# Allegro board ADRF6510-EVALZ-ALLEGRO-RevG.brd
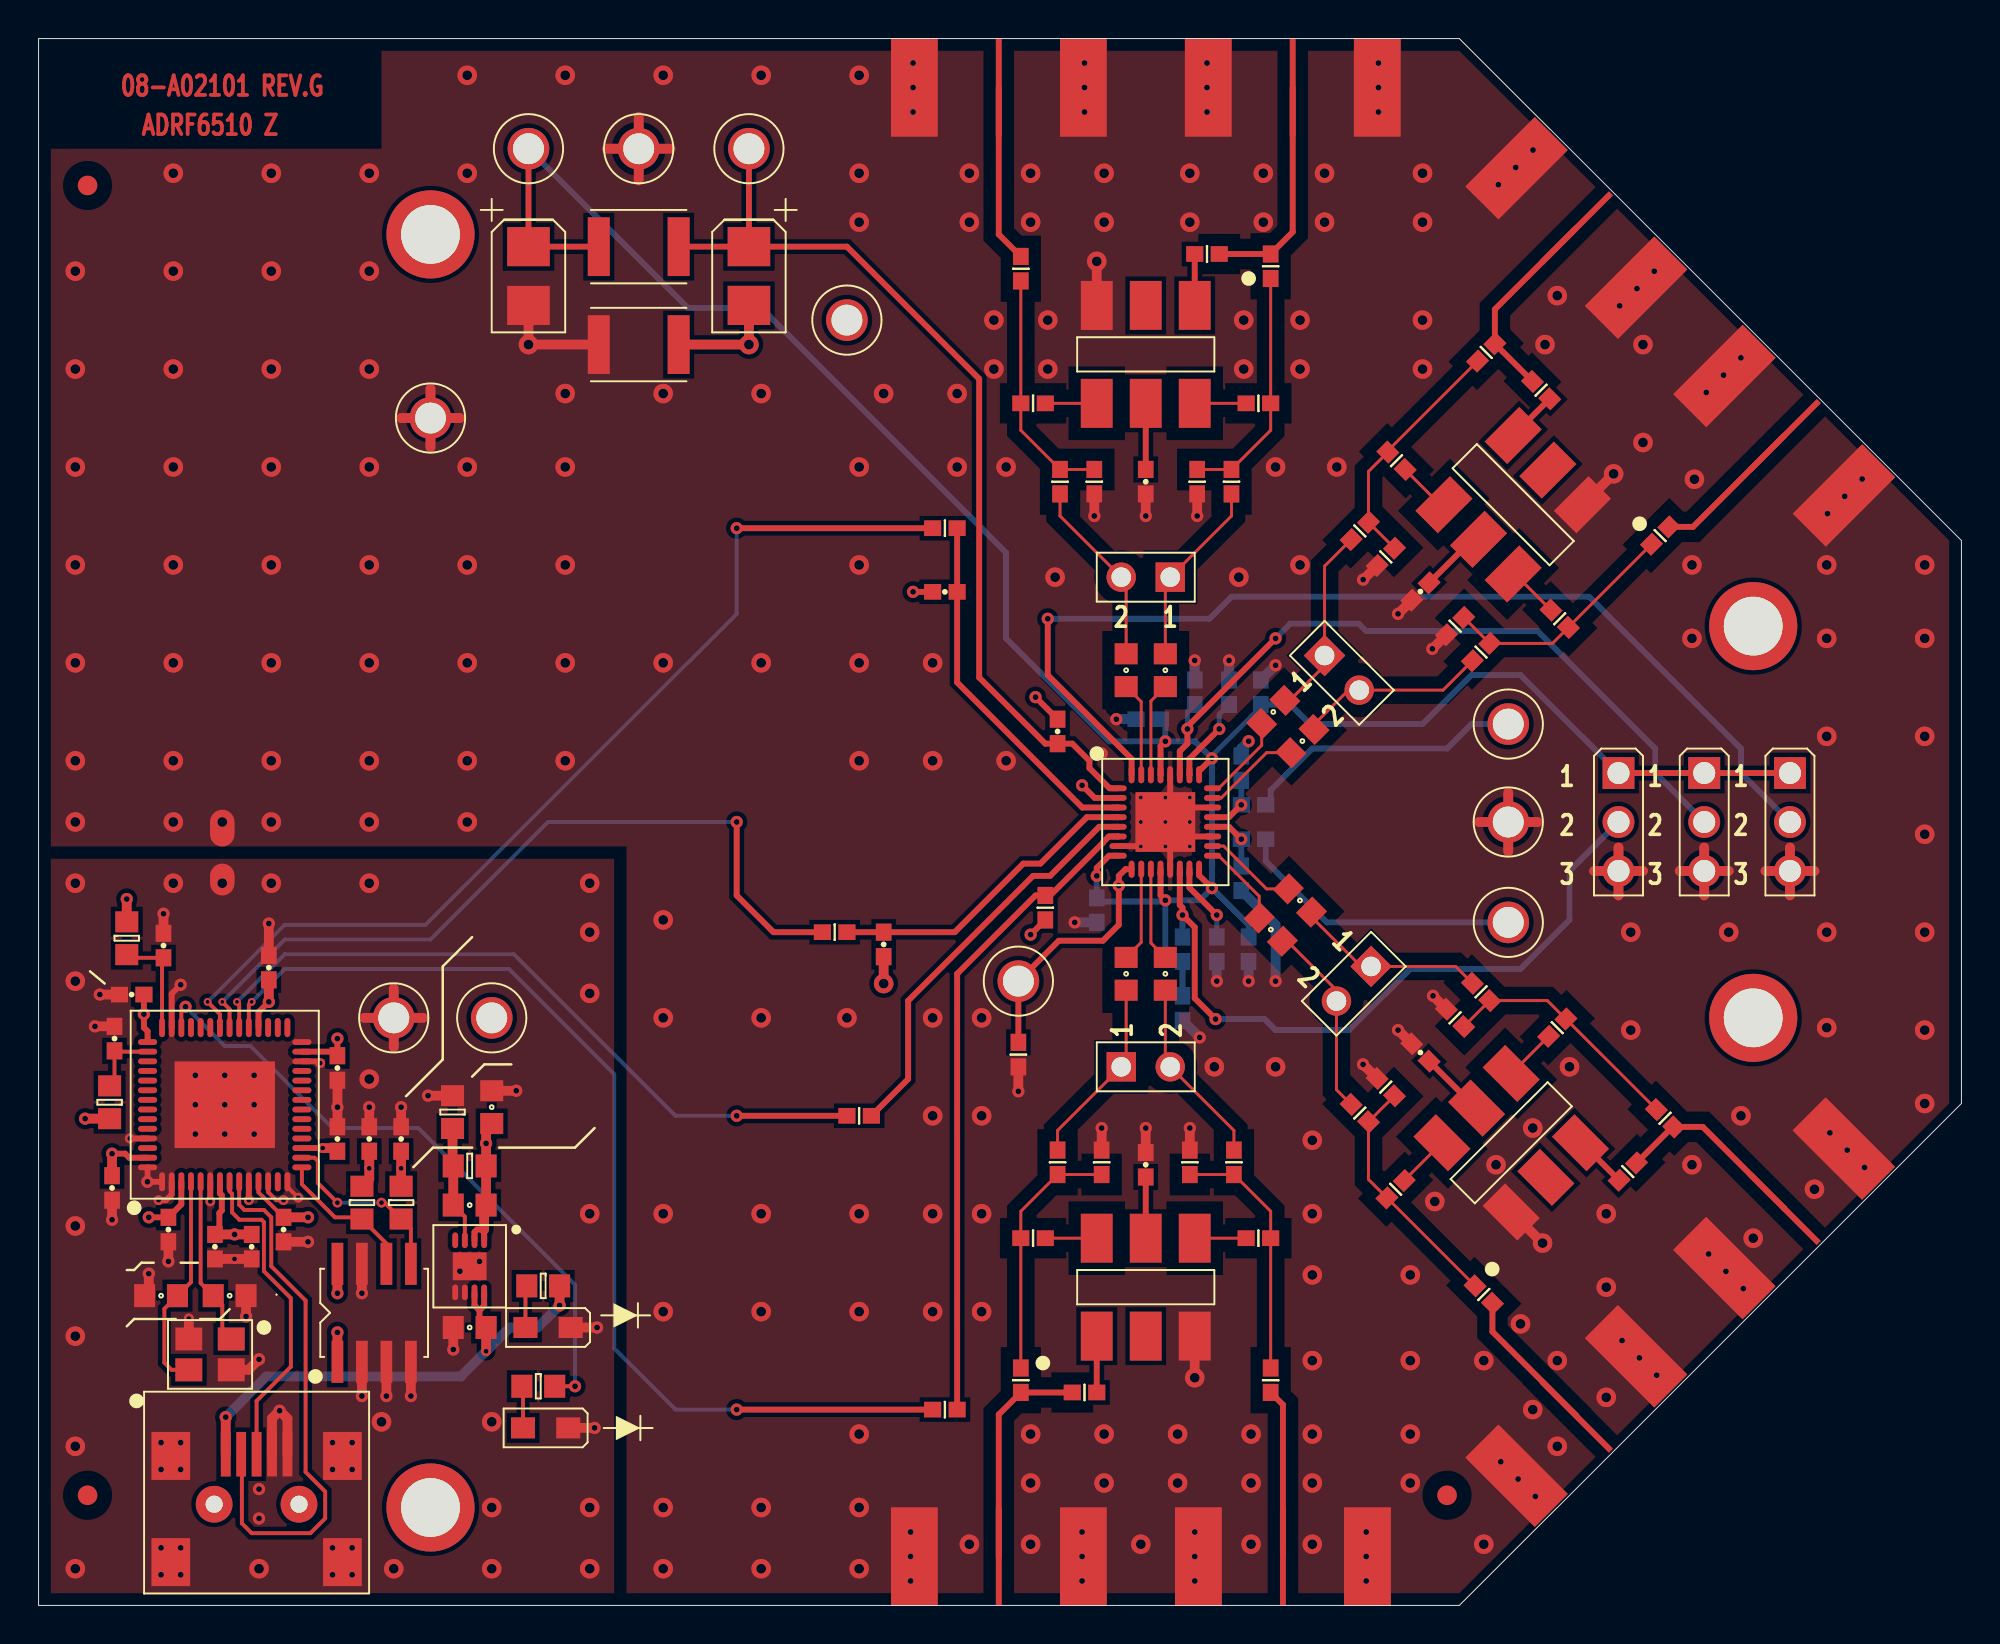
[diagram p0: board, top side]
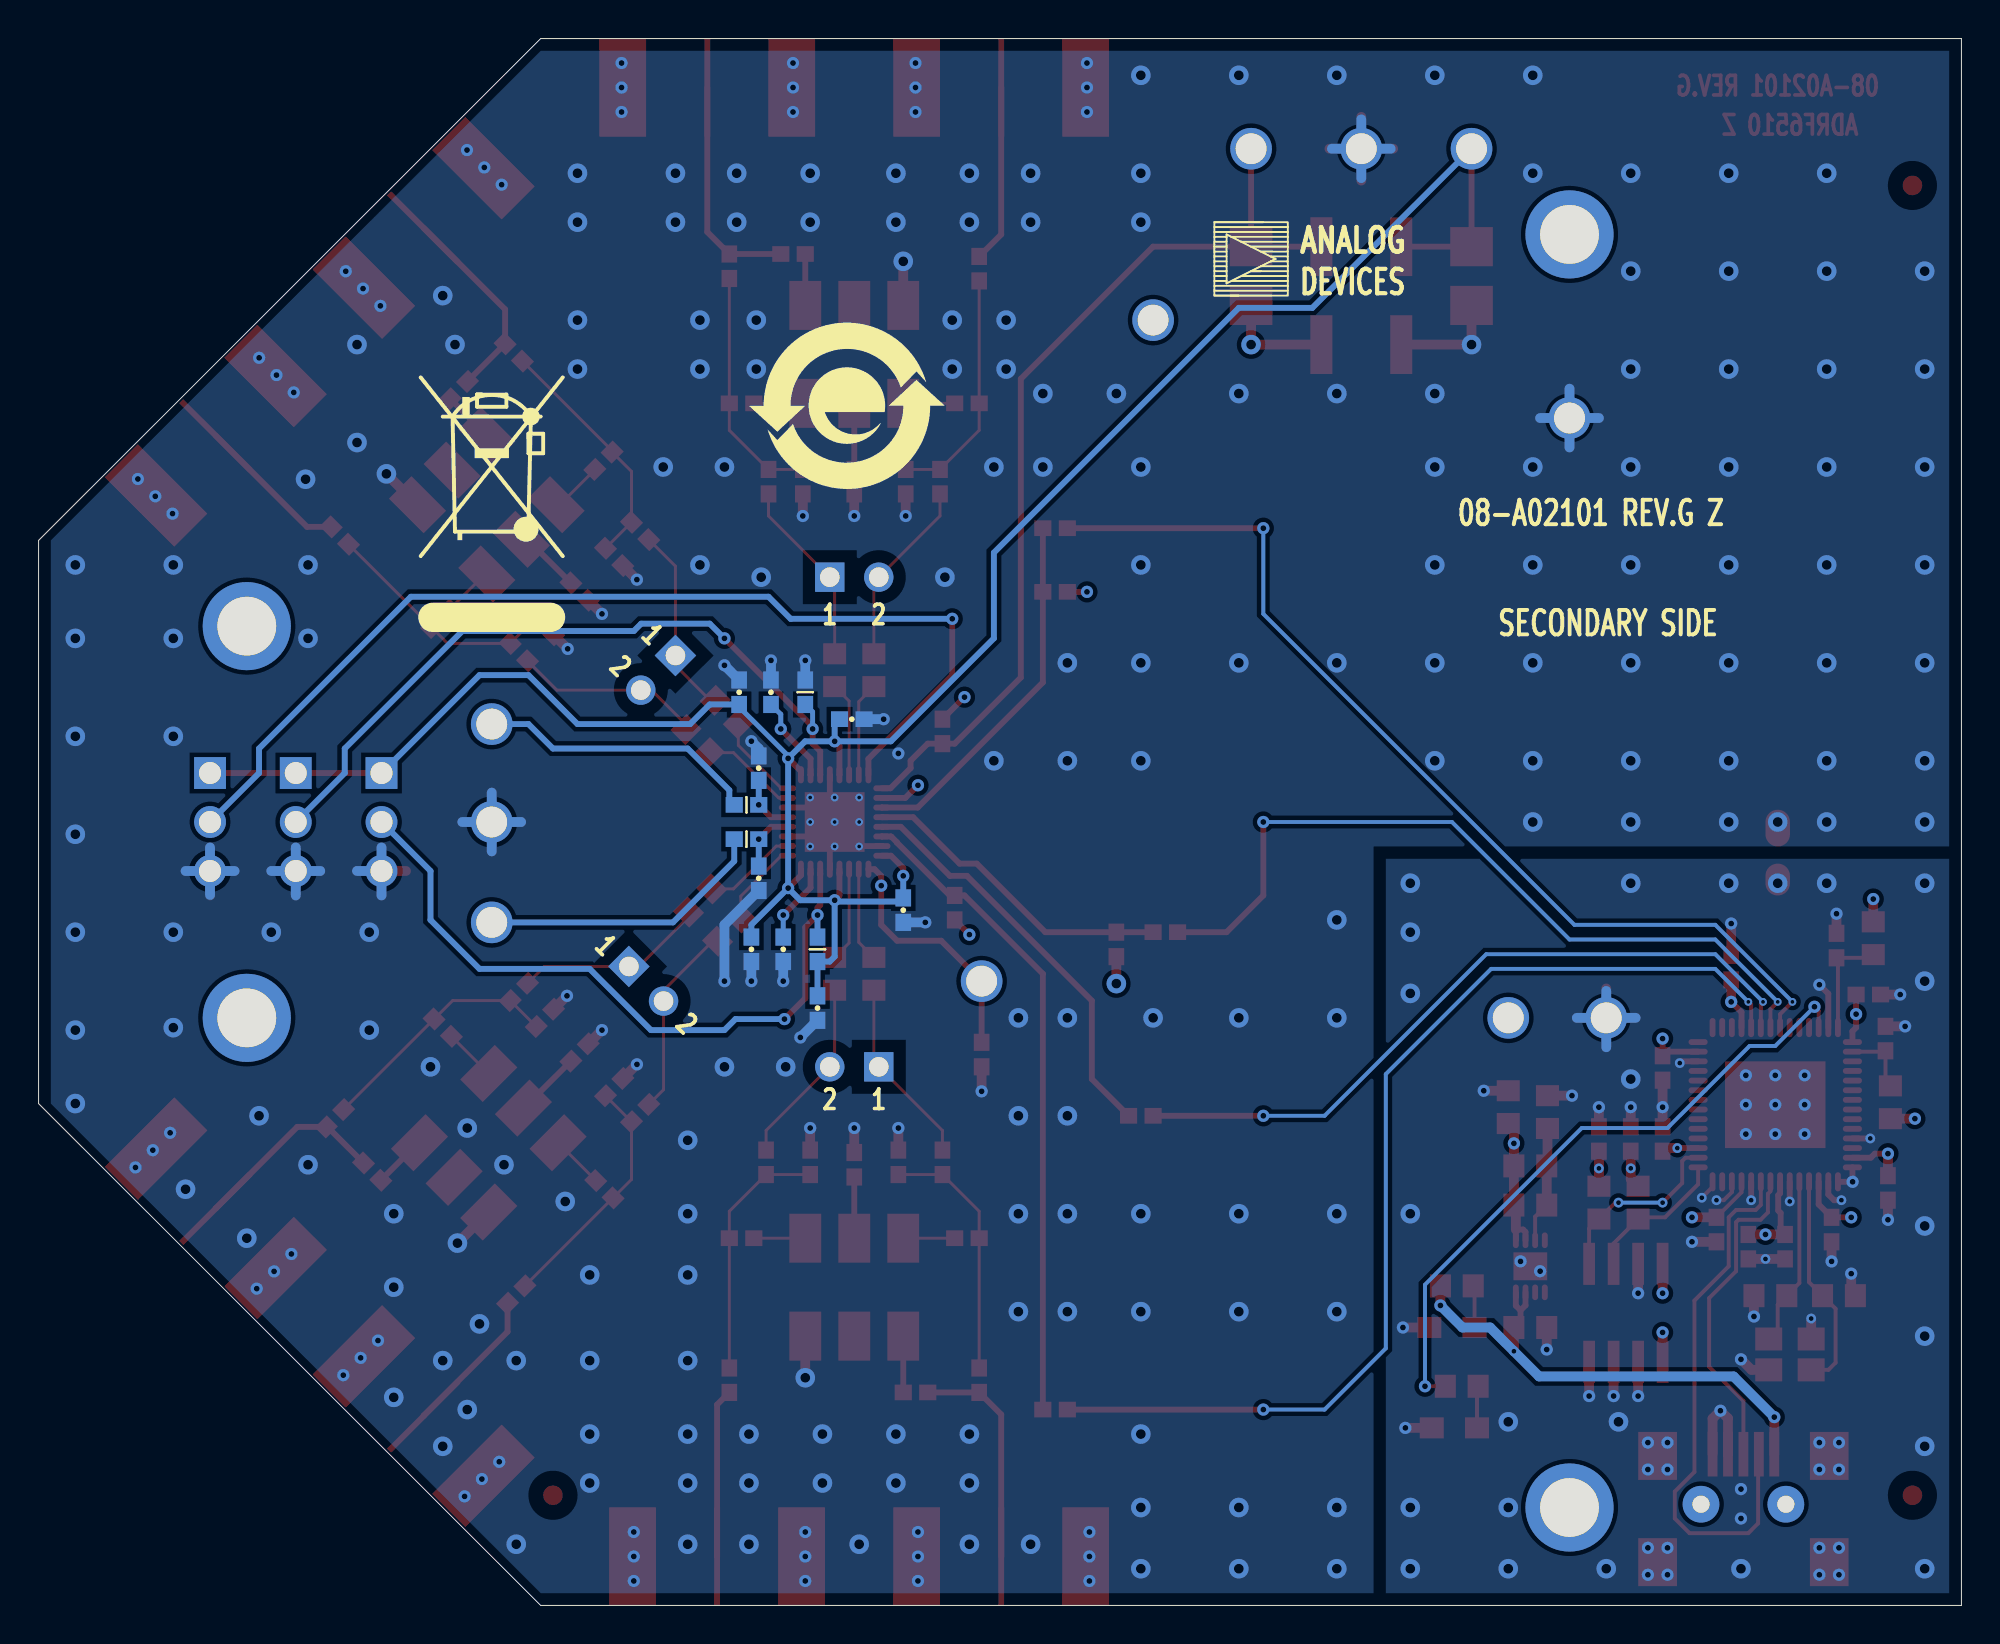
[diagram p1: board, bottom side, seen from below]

Outline 99.69 x 81.28 mm; copper layers: TOP, L2_GND, L3_GND, BOTTOM. Coordinates in mm from the lower left corner of the outline.
Outline path: 0,81.28 0,0 73.66,0 99.69,26.04 99.69,55.25 73.66,81.28 0,81.28

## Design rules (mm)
net group 50_OHMS: nets UNNAMED_2_CNBNC5P_I37_CNTR UNNAMED_2_CNBNC5P_I39_CNTR UNNAMED_2_CNBNC5P_I62_CNTR UNNAMED_2_CNBNC5P_I63_CNTR UNNAMED_2_CNBNC5P_I80_CNTR UNNAMED_2_CNBNC5P_I81_CNTR UNNAMED_2_CNBNC5P_I127_CNTR UNNAMED_2_CNBNC5P_I129_CNTR
net group HIGH_Z: nets UNNAMED_2_ADRF6510_I1_INM1 UNNAMED_2_ADRF6510_I1_INM2 UNNAMED_2_ADRF6510_I1_INP1 UNNAMED_2_ADRF6510_I1_INP2 UNNAMED_2_ADRF6510_I1_OPM1 UNNAMED_2_ADRF6510_I1_OPM2 UNNAMED_2_ADRF6510_I1_OPP1 UNNAMED_2_ADRF6510_I1_OPP2 UNNAMED_2_CAP_I21_N2 UNNAMED_2_CAP_I22_N2 UNNAMED_2_CAP_I59_N2 UNNAMED_2_CAP_I60_N2 UNNAMED_2_CAP_I96_N2 UNNAMED_2_CAP_I97_N2 UNNAMED_2_CAP_I111_N1 UNNAMED_2_CAP_I112_N1 UNNAMED_2_RES_I24_N2 UNNAMED_2_RES_I26_N2 UNNAMED_2_RES_I29_N2 UNNAMED_2_RES_I32_N1 UNNAMED_2_RES_I50_N1 UNNAMED_2_RES_I50_N2 UNNAMED_2_RES_I51_N1 UNNAMED_2_RES_I51_N2 UNNAMED_2_RES_I82_N1 UNNAMED_2_RES_I86_N1 UNNAMED_2_RES_I87_N2 UNNAMED_2_RES_I90_N1 UNNAMED_2_RES_I114_N1 UNNAMED_2_RES_I116_N2 UNNAMED_2_RES_I120_N2 UNNAMED_2_RES_I123_N1

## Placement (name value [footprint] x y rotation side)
C1  10UF  [C3528]  36.83 68.96 270 top
C2  10UF  [C3528]  25.4 68.96 270 top
C3  0.1UF  [C0402]  57.4 22.86 270 top
C4  0.1UF  [C0402]  52.83 45.34 90 top
C5  0.1UF  [C0402]  54.86 36.07 270 bottom
C6  0.1UF  [C0402]  57.4 58.29 90 top
C7  100NF  [C0603H62]  56.39 32.77 270 top
C8  100NF  [C0603H62]  58.42 32.77 270 top
C9  100NF  [C0603H62]  58.42 48.51 270 top
C10  100NF  [C0603H62]  56.39 48.51 270 top
C11  0.1UF  [C0402]  59.31 30.99 270 bottom
C12  0.1UF  [C0402]  57.53 45.97 180 bottom
C13  0.001UF  [C0402]  61.09 34.04 270 bottom
C14  0.001UF  [C0402]  61.72 47.37 90 bottom
C15  0.1UF  [C0402]  62.74 34.04 270 bottom
C16  0.1UF  [C0402]  63.37 47.37 90 bottom
C17  0.1UF  [C0402]  62.36 43.43 270 bottom
C18  0.1UF  [C0402]  62.36 37.72 270 bottom
C19  100NF  [C0603H62]  64.02 46.35 45 top
C20  100NF  [C0603H62]  65.52 44.84 45 top
C21  100NF  [C0603H62]  65.4 36.57 315 top
C22  100NF  [C0603H62]  63.89 35.06 315 top
C23  0.1UF  [C0402]  71.65 52.6 45 top
C24  0.1UF  [C0402]  71.65 28.68 315 top
C27  330pF  [C0402]  46.99 52.58 180 top
C28  330pF  [C0402]  43.81 34.29 270 top
C35  0.1UF  [C0402]  4.83 31.69 180 top
C36  0.1UF  [C0402]  3.81 21.66 270 top
C37  0.1UF  [C0402]  6.48 34.23 90 top
C38  10pF  [C0402]  17.15 24.2 90 top
C39  0.1UF  [C0402]  18.8 24.2 90 top
C40  0.1UF  [C0402]  15.49 24.2 90 top
C41  0.1UF  [C0402]  15.49 27.88 270 top
C42  0.1UF  [C0402]  11.94 33.09 90 top
C44  0.1UF  [C0402]  12.7 19.5 270 top
C45  0.1UF  [C0402]  3.94 29.4 90 top
C46  0.1UF  [C0402]  11.05 18.61 270 top
C47  1UF  [C0603]  22.35 14.42 180 top
C48  10pF  [C0402]  6.73 19.5 270 top
C49  0.1UF  [C0402]  9.14 18.61 270 top
C50  1000pF  [C0603]  22.35 20.77 180 top
C51  22PF  [C0603]  9.91 16.07 0 top
C52  1UF  [C0603]  23.5 25.85 90 top
C54  22PF  [C0603]  6.35 16.07 180 top
COM  GRN  [CNLOOPTP]  76.2 40.64 0 top
COMA  GRN  [CNLOOPTP]  31.12 75.56 0 top
COMB  GRN  [CNLOOPTP]  20.32 61.59 0 top
COMD  VIOLET  [CNLOOPTP]  41.91 66.67 0 top
CR1  SML-210MTT86  [LED0805]  26.42 14.42 180 top
CR2  SML-210MTT86  [LED0805]  26.29 9.21 180 top
DGND  BLK  [CNLOOPTP]  18.41 30.48 270 top
INM1_SE_P  JOHNSON142-0701-851  [CNJOHNSON142-0701-851]  65.02 78.74 90 top
INM2_SE_P  JOHNSON142-0701-851  [CNJOHNSON142-0701-851]  64.52 2.54 270 top
INP1  JOHNSON142-0701-851  [CNJOHNSON142-0701-851]  49.78 78.74 90 top
INP2  JOHNSON142-0701-851  [CNJOHNSON142-0701-851]  49.78 2.54 270 top
L1  33uH  [L1812-3]  31.12 65.41 180 top
L2  33uH  [L1812-3]  31.12 70.48 180 top
NOREF  -  []  697.99 -250.7 0 top
NOREF#2  -  [unnamed#2]  20.32 5.08 0 top
NOREF#3  -  []  73.66 0 90 top
NOREF#4  -  []  0 0 0 top
NOREF#5  -  [unnamed#2]  73.03 5.72 0 top
NOREF#6  -  [unnamed#2]  88.9 30.48 0 top
NOREF#7  -  []  0 0 0 top
NOREF#8  -  []  0 0 0 top
NOREF#9  -  []  -93.98 -259.08 0 top
NOREF#10  -  [unnamed#2]  2.54 73.66 0 top
NOREF#11  -  []  39.37 -116.71 0 top
NOREF#12  -  []  0 0 90 top
NOREF#13  -  []  73.66 0 90 top
NOREF#14  -  []  37.47 92.71 0 top
NOREF#15  -  [unnamed#2]  88.9 50.8 0 top
NOREF#16  -  [unnamed#2]  2.54 5.72 0 top
NOREF#17  -  []  0 0 90 top
NOREF#18  -  [unnamed#2]  20.32 71.12 0 top
NOREF#19  -  []  517.14 -106.05 0 top
NOREF#20  -  []  0 0 0 top
NOREF#21  -  []  283.97 -102.36 0 top
NOREF#22  -  []  0 81.28 270 top
NOREF#23  -  []  504.82 143.13 0 top
NOREF#24  -  []  498.48 -125.1 0 top
NOREF#25  -  []  57.79 62.23 180 bottom
NOREF#26  -  []  66.93 67.39 180 bottom
NOREF#27  -  []  38.73 67.94 180 bottom
OPM1_SE_P  JOHNSON142-0701-851  [CNJOHNSON142-0701-851]  90.51 60.68 45 top
OPM2_SE_P  JOHNSON142-0701-851  [CNJOHNSON142-0701-851]  90.5 20.6 315 top
OPP1  JOHNSON142-0701-851  [CNJOHNSON142-0701-851]  79.73 71.46 45 top
OPP2  JOHNSON142-0701-851  [CNJOHNSON142-0701-851]  79.73 9.82 315 top
P1  BERG69157-102  [CNBERG69157-102]  56.13 27.94 0 top
P2  MOLEX22-03-2031  [CNMOLEX22-03-2031]  90.81 43.18 270 top
P3  MOLEX22-03-2031  [CNMOLEX22-03-2031]  86.36 43.18 270 top
P4  MOLEX22-03-2031  [CNMOLEX22-03-2031]  81.92 43.18 270 top
P5  897-43-005-00-100001  [CNTYCO-1734035-2]  11.3 6.93 0 top
P6  BERG69157-102  [CNBERG69157-102]  58.67 53.34 180 top
P7  BERG69157-102  [CNBERG69157-102]  66.67 49.28 315 top
P8  BERG69157-102  [CNBERG69157-102]  69.09 33.15 225 top
R1  10K  [R0402]  52.2 36.2 270 top
R2  0  [R0402]  50.8 28.58 90 top
R3  10K  [R0402]  59.31 34.04 270 bottom
R4  10K  [R0402]  59.94 47.37 90 bottom
R5  0  [R0402]  62.99 41.53 0 bottom
R6  0  [R0402]  62.99 39.75 0 bottom
R7  300  [R0402]  68.5 55.74 45 top
R8  300  [R0402]  74.79 49.45 45 top
R9  300  [R0402]  74.79 31.83 315 top
R10  300  [R0402]  68.5 25.54 315 top
R11  TBD0402  [R0402]  73.44 50.8 225 top
R12  TBD0402  [R0402]  69.85 54.39 225 top
R13  TBD0402  [R0402]  69.85 26.89 135 top
R14  TBD0402  [R0402]  73.44 30.48 135 top
R19  0  [R0402]  70.4 59.38 315 top
R20  0  [R0402]  78.87 51.18 315 top
R29  100  [R0402]  46.99 55.88 0 top
R30  100  [R0402]  41.28 34.92 0 top
R31  0  [R0402]  60.58 70.1 180 top
R32  0  [R0402]  54.23 11.05 0 top
R33  0  [R0402]  42.55 25.4 0 top
R34  0  [R0402]  46.99 10.16 0 top
R35  0  [R0402]  78.74 29.97 225 top
R36  0  [R0402]  70.36 21.59 225 top
R37  TBD0402  [R0402]  75.06 65 45 top
R38  TBD0402  [R0402]  84.33 25.27 315 top
R39  TBD0402  [R0402]  84.07 55.5 45 top
R40  TBD0402  [R0402]  74.93 16.13 315 top
R41  0  [R0402]  77.9 63.04 315 top
R42  0  [R0402]  82.4 22.5 225 top
R43  TBD0402  [R0402]  50.93 69.34 90 top
R44  TBD0402  [R0402]  63.88 11.68 270 top
R45  TBD0402  [R0402]  63.88 69.47 90 top
R46  TBD0402  [R0402]  50.93 11.68 270 top
R47  0  [R0402]  63.25 62.36 180 top
R48  0  [R0402]  51.56 62.36 180 top
R49  0  [R0402]  51.56 19.05 0 top
R50  0  [R0402]  63.25 19.05 0 top
R51  TBD0402  [R0402]  55.12 22.99 90 top
R52  TBD0402  [R0402]  59.69 22.99 90 top
R53  0  [R0402]  52.83 22.99 270 top
R54  0  [R0402]  61.98 22.99 270 top
R55  TBD0402  [R0402]  60.07 58.29 270 top
R56  TBD0402  [R0402]  54.74 58.29 270 top
R57  0  [R0402]  61.85 58.29 90 top
R58  0  [R0402]  52.96 58.29 90 top
R59  2K  [R0603]  18.8 20.9 270 top
R60  2K  [R0603]  16.76 20.9 270 top
R61  2K  [R0603]  25.91 11.37 180 top
R62  100K  [R0603]  3.68 26.1 90 top
R64  100K  [R0603]  4.57 34.61 270 top
R65  2K  [R0603]  26.16 16.58 180 top
R69  78.7K  [R0603]  21.46 25.59 90 top
R70  140K  [R0603]  22.35 22.8 180 top
SNS1  SNS  [NCSNS50MIL]  9.52 40.01 270 top
T1  ADT8-1T+  [MINICKCD637]  57.4 64.9 180 top
T2  ADT8-1T+  [MINICKCD637]  57.4 16.51 0 top
T3  ADT8-1T+  [MINICKCD637]  76.45 57.1 135 top
T4  ADT8-1T+  [MINICKCD637]  76.35 24 45 top
TRIM  BLK  [CNLOOPTP]  50.8 32.38 0 top
U1  ADRF6510ACPZ  [QFN32_5X5_PAD3_1X3_1]  58.42 40.64 270 top
U2  24LC64-I-SN  [SO8]  17.4 15.18 0 top
U3  ADP3334ACPZ  [QFN8_3X3_PAD1_75X1_45]  22.35 17.59 180 top
U4  CY7C68013A-56LTXC  [QFN56_8X8_PAD5_2X4_5]  9.65 25.98 0 top
UNK3V3_USB  BLK  [CNLOOPTP]  23.5 30.48 270 top
VGAIN  WHT  [CNLOOPTP]  76.2 45.72 0 top
VOCM  ORG  [CNLOOPTP]  76.2 35.43 0 top
VPS  RED  [CNLOOPTP]  25.4 75.56 0 top
VPSD  YEL  [CNLOOPTP]  36.83 75.56 0 top
Y1  24.000000MEGHZ  [XTALNX3225]  8.89 13.02 180 top

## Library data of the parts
C1 C2 = CAPP: User Part Number: UPN; Tolerance: 10; part number: CAPP_SM-10UF,16V,10,E000695,C3528; tolerance: 10
C3-C6 C11 C12 C15-C18 C23 C24 C35-C37 C39-C42 C44-C46 C49 = CAP: Tolerance: 10; User Part Number: UPN; alternate symbols: (C0402H22_ALT,C0201-2); part number: CAP_SM-0.1UF,16V,10,E007200,C0402; tolerance: 10
C7-C10 C19-C22 = CAP: Tolerance: 20; User Part Number: UPN; alternate symbols: (C0402H22_ALT,C0201-2); part number: CAP_SM-100NF,25V,20,E000372,C0603H62; tolerance: 20
C13 C14 = CAP: Tolerance: 10; User Part Number: UPN; alternate symbols: (C0402H22_ALT,C0201-2); part number: CAP_SM-0.001UF,50V,10,E006276,C0402; tolerance: 10
C27 C28 = CAP: Tolerance: 10; User Part Number: UPN; alternate symbols: (C0402H22_ALT,C0201-2); part number: CAP_SM-330PF,50V,10,E012647,C0402; tolerance: 10
C38 C48 = CAP: Tolerance: 5; User Part Number: UPN; alternate symbols: (C0402H22_ALT,C0201-2); part number: CAP_SM-10PF,50V,5,E007982,C0402; tolerance: 5
C47 C52 = CAP: Tolerance: 10; User Part Number: UPN; alternate symbols: (C0402H22_ALT,C0201-2); part number: CAP_SM-1UF,25V,10,E006992,C0603; tolerance: 10
C50 = CAP: Tolerance: 5; User Part Number: UPN; alternate symbols: (C0402H22_ALT,C0201-2); part number: CAP_SM-1000PF,50V,5,E007908,C0603; tolerance: 5
C51 C54 = CAP: Tolerance: 5; User Part Number: UPN; alternate symbols: (C0402H22_ALT,C0201-2); part number: CAP_SM-22PF,50V,5,E000411,C0603; tolerance: 5
COM COMA COMB = CNTP1P: User Part Number: UPN; part number: CNTP1P_TH-GRN,E000952,CNLOOPTP
COMD = CNTP1P: User Part Number: UPN; part number: CNTP1P_TH-VIOLET,E000954,CNLOOPTP
CR1 CR2 = DIOLED: Tolerance: N/A; User Part Number: UPN; part number: DIOLED_SM-SML-210MTT86,2.2V,N/A,E011181,LED0805; tolerance: N/A
DGND TRIM UNK3V3_USB = CNTP1P: User Part Number: UPN; part number: CNTP1P_TH-BLK,E000948,CNLOOPTP
INM1_SE_P INM2_SE_P INP1 INP2 OPM1_SE_P OPM2_SE_P OPP1 OPP2 = CNBNC5P: User Part Number: UPN; part number: CNBNC5P_SM-JOHNSON142-0701-851,E000923,CNJOHNSON142-0701-851
L1 L2 = IND: User Part Number: UPN; Tolerance: 5; alternate symbols: (L0402-2,L0603_ALT); part number: IND_SM-33UH,5,E015062,L1812-3; tolerance: 5
P1 P6-P8 = CN2P: User Part Number: UPN; part number: CN2P_TH-BERG69157-102,E000791,CNBERG69157-102
P2-P4 = CN3P: User Part Number: UPN; part number: CN3P_TH-MOLEX22-03-2031,E000811,CNMOLEX22-03-2031
P5 = CN5P_4GND: User Part Number: UPN; part number: CN5P_4GND_SM-897-43-005-00-100001,E012238,CNTYCO-1734035-2
R1 R3 R4 = RES: Tolerance: 1; User Part Number: UPN; alternate symbols: (RRAD984L1500W75H520LD32); part number: RES_SM-10K,1/16W,1,E003751,R0402; tolerance: 1
R2 R5 R6 R19 R20 R31-R36 R41 R42 R47-R50 R53 R54 R57 R58 = RES: Tolerance: 5; User Part Number: UPN; alternate symbols: (RRAD984L1500W75H520LD32); part number: RES_SM-0,1/16W,5,E003438,R0402; tolerance: 5
R7-R10 = RES: Tolerance: 5; User Part Number: UPN; alternate symbols: (RRAD984L1500W75H520LD32); part number: RES_SM-300,1/16W,5,E003444,R0402; tolerance: 5
R11-R14 R37-R40 R43-R46 R51 R52 R55 R56 = RES: User Part Number: UPN; alternate symbols: (RRAD984L1500W75H520LD32); part number: RES_SM-TBD0402,TBD0402,TBD0402,E004049,R0402
R29 R30 = RES: Tolerance: 1; User Part Number: UPN; alternate symbols: (RRAD984L1500W75H520LD32); part number: RES_SM-100,1/16W,1,E003760,R0402; tolerance: 1
R59-R61 R65 = RES: Tolerance: 1; User Part Number: UPN; alternate symbols: (RRAD984L1500W75H520LD32); part number: RES_SM-2K,1/10W,1,E003711,R0603; tolerance: 1
R62 R64 = RES: Tolerance: 1; User Part Number: UPN; alternate symbols: (RRAD984L1500W75H520LD32); part number: RES_SM-100K,1/10W,1,E010279,R0603; tolerance: 1
R69 = RES: Tolerance: 1; User Part Number: UPN; alternate symbols: (RRAD984L1500W75H520LD32); part number: RES_SM-78.7K,1/10W,1,E010308,R0603; tolerance: 1
R70 = RES: Tolerance: 1; User Part Number: UPN; alternate symbols: (RRAD984L1500W75H520LD32); part number: RES_SM-140K,1/10W,1,E006289,R0603; tolerance: 1
SNS1 = NCSENSE: User Part Number: UPN; part number: NCSENSE_SM-SNS,E005619,NCSNS50MIL
T1-T4 = XFMRMCCD542KS: User Part Number: UPN; part number: XFMRMCCD542KS_SM-ADT8-1T+,E007857,MINICKCD637
U1 = ADRF6510: User Part Number: UPN; part number: ADRF6510_SM-ADRF6510ACPZ,E015019,QFN32_5X5_PAD3_1X3_1,N/A
U2 = ICIS24C64: User Part Number: UPN; part number: ICIS24C64_SM-24LC64-I-SN,E002004,SO8
U3 = ADP3334: User Part Number: UPN; part number: ADP3334_SM-ADP3334ACPZ,E005986,QFN8_3X3_PAD1_75X1_45,N/A
U4 = ICCY7C6801XA: User Part Number: UPN; part number: ICCY7C6801XA_SM-CY7C68013A-56LTXC,E013815,QFN56_8X8_PAD5_2X4_5
VGAIN = CNTP1P: User Part Number: UPN; part number: CNTP1P_TH-WHT,E000946,CNLOOPTP
VOCM = CNTP1P: User Part Number: UPN; part number: CNTP1P_TH-ORG,E000949,CNLOOPTP
VPS = CNTP1P: User Part Number: UPN; part number: CNTP1P_TH-RED,E000947,CNLOOPTP
VPSD = CNTP1P: User Part Number: UPN; part number: CNTP1P_TH-YEL,E000945,CNLOOPTP
Y1 = XTALNX3225: User Part Number: UPN; part number: XTALNX3225_SM-24.000000MEGHZ,E007060,XTALNX3225

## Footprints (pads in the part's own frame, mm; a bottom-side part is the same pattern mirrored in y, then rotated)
C0402
  rect 0.889x0.813 smd: 1(-0.635,0) 2(0.635,0)
C0603
  rect 1.092x1.194 smd: 1(-0.851,0) 2(0.851,0)
C0603H62
  rect 1.092x1.194 smd: 1(-0.851,0) 2(0.851,0)
C3528
  rect 2.032x2.21 smd: N(1.524,0) P(-1.524,0)
CNBERG69157-102
  rect 1.524x1.524 hole 1.016: 1(0,0)
  round 1.524 hole 1.016: 2(2.54,0)
CNJOHNSON142-0701-851
  rect 5.08x0.305 smd: 1(0,0)
  rect 5.08x2.413 smd: 2(0,4.381) 3(0,4.381) 4(0,-4.381) 5(0,-4.381)
CNLOOPTP
  round 2.159 hole 1.6: 1(0,0)
CNMOLEX22-03-2031
  rect 1.651x1.651 hole 1.143: 1(0,0)
  round 1.651 hole 1.143: 2(2.54,0) 3(5.08,0)
CNTYCO-1734035-2
  round 1.905 hole 0.889 unplated: (-2.2,-1.675) (2.2,-1.675)
  rect 0.508x2.311 smd: 1(-1.6,0.919) 2(-0.8,0.919) 3(0,0.919) 4(0.8,0.919) 5(1.6,0.919)
  rect 2.007x2.489 smd: G1(-4.45,0.83) G2(4.45,0.83) G3(4.45,-4.68) G4(-4.45,-4.68)
L1812-3
  rect 1.143x3.048 smd: 1(-2.07,0) 2(2.07,0)
LED0805
  rect 1.245x1.092 smd: A(1.172,0) C(-1.172,0)
MINICKCD637
  rect 1.651x2.54 smd: 1(-2.54,-2.54) 2(0,-2.54) 3(2.54,-2.54) 4(2.54,2.54) 5(0,2.54) 6(-2.54,2.54)
NCSNS50MIL
  round 0.127 smd: 1(0,0) 2(2.032,0)
QFN8_3X3_PAD1_75X1_45
  oval 0.305x0.813 smd: 1(-0.75,-1.35) 2(-0.25,-1.35) 3(0.25,-1.35) 4(0.75,-1.35) 5(0.75,1.35) 6(0.25,1.35) 7(-0.25,1.35) 8(-0.75,1.35)
  rect 1.753x1.448 smd: PAD(0,0)
QFN32_5X5_PAD3_1X3_1
  oval 0.305x0.889 smd: 1(-1.75,-2.45) 2(-1.25,-2.45) 3(-0.75,-2.45) 4(-0.25,-2.45) 5(0.25,-2.45) 6(0.75,-2.45) 7(1.25,-2.45) 8(1.75,-2.45) 17(1.75,2.45) 18(1.25,2.45) 19(0.75,2.45) 20(0.25,2.45) 21(-0.25,2.45) 22(-0.75,2.45) 23(-1.25,2.45) 24(-1.75,2.45)
  oval 0.889x0.305 smd: 9(2.45,-1.75) 10(2.45,-1.25) 11(2.45,-0.75) 12(2.45,-0.25) 13(2.45,0.25) 14(2.45,0.75) 15(2.45,1.25) 16(2.45,1.75) 25(-2.45,1.75) 26(-2.45,1.25) 27(-2.45,0.75) 28(-2.45,0.25) 29(-2.45,-0.25) 30(-2.45,-0.75) 31(-2.45,-1.25) 32(-2.45,-1.75)
  rect 3.099x3.099 smd: PAD(0,0)
QFN56_8X8_PAD5_2X4_5
  oval 0.305x0.991 smd: 1(-3.25,-4) 2(-2.75,-4) 3(-2.25,-4) 4(-1.75,-4) 5(-1.25,-4) 6(-0.75,-4) 7(-0.25,-4) 8(0.25,-4) 9(0.75,-4) 10(1.25,-4) 11(1.75,-4) 12(2.25,-4) 13(2.75,-4) 14(3.25,-4) 29(3.25,4) 30(2.75,4) 31(2.25,4) 32(1.75,4) 33(1.25,4) 34(0.75,4) 35(0.25,4) 36(-0.25,4) 37(-0.75,4) 38(-1.25,4) 39(-1.75,4) 40(-2.25,4) 41(-2.75,4) 42(-3.25,4)
  oval 0.991x0.305 smd: 15(4,-3.25) 16(4,-2.75) 17(4,-2.25) 18(4,-1.75) 19(4,-1.25) 20(4,-0.75) 21(4,-0.25) 22(4,0.25) 23(4,0.75) 24(4,1.25) 25(4,1.75) 26(4,2.25) 27(4,2.75) 28(4,3.25) 43(-4,3.25) 44(-4,2.75) 45(-4,2.25) 46(-4,1.75) 47(-4,1.25) 48(-4,0.75) 49(-4,0.25) 50(-4,-0.25) 51(-4,-0.75) 52(-4,-1.25) 53(-4,-1.75) 54(-4,-2.25) 55(-4,-2.75) 56(-4,-3.25)
  rect 5.207x4.496 smd: PAD(0,0)
R0402
  rect 0.889x0.813 smd: 1(-0.635,0) 2(0.635,0)
R0603
  rect 1.092x1.194 smd: 1(-0.851,0) 2(0.851,0)
SO8
  rect 0.61x2.184 smd: 1(-1.905,-2.54) 2(-0.635,-2.54) 3(0.635,-2.54) 4(1.905,-2.54) 5(1.905,2.54) 6(0.635,2.54) 7(-0.635,2.54) 8(-1.905,2.54)
unnamed#2
  round 4.572 hole 3.048 unplated: (0,0)
XTALNX3225
  rect 1.397x1.194 smd: 1(-1.1,-0.8) 2(1.1,-0.8) 3(1.1,0.8) 4(-1.1,0.8)

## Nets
3V3_USB: C35.1(N1) C36.1(N1) C38.1(N1) C39.1(N1) C40.1(N1) C41.1(N1) C42.1(N1) C44.1(N1) C46.1(N1) C48.1(N1) C49.1(N1) C50.1(N1) C52.1(N1) R59.1(N1) R60.1(N1) R62.1(N1) R64.1(N1) R70.1(N1) U2.1(A0) U2.8(VCC) U3.1(OUT1) U3.2(OUT2) U4.3(AVCC1) U4.7(AVCC2) U4.11(VCC1) U4.17(VCC2) U4.27(VCC3) U4.32(VCC4) U4.43(VCC5) U4.55(VCC6) UNK3V3_USB.1
5V_USB: C47.1(N1) P5.1(N1) R65.1(N1) U3.7(IN1) U3.8(IN2)
AGND: C2.N(N2) C3.1(N1) C5.2(N2) C6.1(N1) C11.2(N2) C12.2(N2) C13.2(N2) C14.2(N2) C15.2(N2) C16.2(N2) C17.1(N1) C18.2(N2) C23.1(N1) C24.1(N1) COM.1(N1) COMA.1(N1) COMB.1(N1) INM1_SE_P.2(SH1) INM1_SE_P.3(SH2) INM1_SE_P.4(SH3) INM1_SE_P.5(SH4) INM2_SE_P.2(SH1) INM2_SE_P.3(SH2) INM2_SE_P.4(SH3) INM2_SE_P.5(SH4) INP1.2(SH1) INP1.3(SH2) INP1.4(SH3) INP1.5(SH4) INP2.2(SH1) INP2.3(SH2) INP2.4(SH3) INP2.5(SH4) L1.2(N2) OPM1_SE_P.2(SH1) OPM1_SE_P.3(SH2) OPM1_SE_P.4(SH3) OPM1_SE_P.5(SH4) OPM2_SE_P.2(SH1) OPM2_SE_P.3(SH2) OPM2_SE_P.4(SH3) OPM2_SE_P.5(SH4) OPP1.2(SH1) OPP1.3(SH2) OPP1.4(SH3) OPP1.5(SH4) OPP2.2(SH1) OPP2.3(SH2) OPP2.4(SH3) OPP2.5(SH4) P2.3(N3) P3.3(N3) P4.3(N3) R2.1(N1) R4.2(N2) R11.2(N2) R12.2(N2) R13.2(N2) R14.2(N2) R51.2(N2) R52.2(N2) R55.2(N2) R56.2(N2) SNS1.1(N1) T1.3(PRIP) T2.3(PRIP) T3.1(PRIN) T4.1(PRIN) U1.7(COM) U1.13(COM2) U1.19(COM3) U1.22(COM4) U1.28(COM5) U1.PAD
DGND: C1.N(N2) C4.2(N2) C27.2(N2) C28.2(N2) C35.2(N2) C36.2(N2) C37.2(N2) C38.2(N2) C39.2(N2) C40.2(N2) C41.2(N2) C42.2(N2) C44.2(N2) C45.2(N2) C46.2(N2) C47.2(N2) C48.2(N2) C49.2(N2) C51.2(N2) C52.2(N2) C54.2(N2) COMD.1(N1) CR1.C(N) CR2.C(N) DGND.1(N1) L1.1(N1) P5.4(N4) P5.5(N5) P5.G1(GND1) P5.G2(GND2) P5.G3(GND3) P5.G4(GND4) R1.2(N2) R69.2(N2) SNS1.2(N2) U1.2(COMD) U2.2(A1) U2.3(A2) U2.4(GND) U2.7(WC*) U3.5(GND) U3.6(SD_N) U3.PAD U4.1(RDY0_SLRD) U4.2(RDY1_SLWR) U4.6(AGND1) U4.10(AGND2) U4.12(GND1) U4.14(RESERVED) U4.26(GND2) U4.28(GND3) U4.41(GND4) U4.53(GND5) U4.56(GND6) U4.PAD Y1.2(CASE1) Y1.4(CASE2)
CLK: R30.1(N1) U4.35(PA2_SLOE)
DATA: R33.1(N1) U4.34(PA1_INT1_N)
LE: R29.1(N1) U4.36(PA3_WU2)
SDO: R34.1(N1) U4.33(PA0_INT0_N)
TRIM: R2.2(N2) TRIM.1(N1) U1.9(COM1)
UNNAMED_2_ADRF6510_I1_CLK: C28.1(N1) R30.2(N2) U1.4(CLK)
UNNAMED_2_ADRF6510_I1_DATA: R33.2(N2) U1.5(DATA)
UNNAMED_2_ADRF6510_I1_ENBL: P2.2(N2) U1.32(ENBL)
UNNAMED_2_ADRF6510_I1_GAIN: C17.2(N2) R5.1(N1) U1.21(GAIN)
UNNAMED_2_ADRF6510_I1_GNSW: P3.2(N2) R4.1(N1) U1.27(GNSW)
UNNAMED_2_ADRF6510_I1_INM1: C9.2(N2) U1.30(INM1)
UNNAMED_2_ADRF6510_I1_INM2: C8.1(N1) U1.11(INM2)
UNNAMED_2_ADRF6510_I1_INP1: C10.2(N2) U1.31(INP1)
UNNAMED_2_ADRF6510_I1_INP2: C7.1(N1) U1.10(INP2)
UNNAMED_2_ADRF6510_I1_LE: C27.1(N1) R29.2(N2) U1.3(LE)
UNNAMED_2_ADRF6510_I1_OFDS: P4.2(N2) R3.1(N1) U1.14(OFDS)
UNNAMED_2_ADRF6510_I1_OFS1: C14.1(N1) U1.26(OFS1)
UNNAMED_2_ADRF6510_I1_OFS2: C13.1(N1) U1.15(OFS2)
UNNAMED_2_ADRF6510_I1_OPM1: C20.1(N1) U1.23(OPM1)
UNNAMED_2_ADRF6510_I1_OPM2: C21.1(N1) U1.18(OPM2)
UNNAMED_2_ADRF6510_I1_OPP1: C19.1(N1) U1.24(OPP1)
UNNAMED_2_ADRF6510_I1_OPP2: C22.1(N1) U1.17(OPP2)
UNNAMED_2_ADRF6510_I1_SDO: R1.1(N1) R34.2(N2) U1.6(SDO)
UNNAMED_2_ADRF6510_I1_VOCM: C18.1(N1) R6.1(N1) U1.20(VOCM)
UNNAMED_2_CAP_I21_N2: C8.2(N2) P1.2(N2) R54.1(N1)
UNNAMED_2_CAP_I22_N2: C7.2(N2) P1.1(N1) R53.1(N1)
UNNAMED_2_CAP_I31_N2: C3.2(N2) T2.5(SECCT)
UNNAMED_2_CAP_I52_N2: C24.2(N2) T4.5(SECCT)
UNNAMED_2_CAP_I59_N2: C21.2(N2) P8.1(N1) R9.1(N1)
UNNAMED_2_CAP_I60_N2: C22.2(N2) P8.2(N2) R10.1(N1)
UNNAMED_2_CAP_I89_N2: C23.2(N2) T3.5(SECCT)
UNNAMED_2_CAP_I96_N2: C19.2(N2) P7.1(N1) R7.1(N1)
UNNAMED_2_CAP_I97_N2: C20.2(N2) P7.2(N2) R8.1(N1)
UNNAMED_2_CAP_I111_N1: C9.1(N1) P6.1(N1) R57.1(N1)
UNNAMED_2_CAP_I112_N1: C10.1(N1) P6.2(N2) R58.1(N1)
UNNAMED_2_CAP_I121_N2: C6.2(N2) T1.5(SECCT)
UNNAMED_2_CNBNC5P_I37_CNTR: INP2.1(CNTR) R32.1(N1) R46.2(N2)
UNNAMED_2_CNBNC5P_I39_CNTR: INM2_SE_P.1(CNTR) R44.2(N2)
UNNAMED_2_CNBNC5P_I62_CNTR: OPM2_SE_P.1(CNTR) R38.2(N2) R42.1(N1)
UNNAMED_2_CNBNC5P_I63_CNTR: OPP2.1(CNTR) R40.2(N2)
UNNAMED_2_CNBNC5P_I80_CNTR: OPP1.1(CNTR) R37.2(N2) R41.1(N1)
UNNAMED_2_CNBNC5P_I81_CNTR: OPM1_SE_P.1(CNTR) R39.2(N2)
UNNAMED_2_CNBNC5P_I127_CNTR: INM1_SE_P.1(CNTR) R31.1(N1) R45.2(N2)
UNNAMED_2_CNBNC5P_I129_CNTR: INP1.1(CNTR) R43.2(N2)
UNNAMED_2_RES_I24_N2: R46.1(N1) R49.1(N1) R51.1(N1) R53.2(N2)
UNNAMED_2_RES_I26_N2: R44.1(N1) R50.2(N2) R52.1(N1) R54.2(N2)
UNNAMED_2_RES_I29_N2: R49.2(N2) T2.6(SECN)
UNNAMED_2_RES_I32_N1: R50.1(N1) T2.4(SECP)
UNNAMED_2_RES_I34_N2: R32.2(N2) T2.1(PRIN)
UNNAMED_2_RES_I50_N1: R9.2(N2) R14.1(N1) R35.1(N1) R38.1(N1)
UNNAMED_2_RES_I50_N2: R35.2(N2) T4.4(SECP)
UNNAMED_2_RES_I51_N1: R36.1(N1) T4.6(SECN)
UNNAMED_2_RES_I51_N2: R10.2(N2) R13.1(N1) R36.2(N2) R40.1(N1)
UNNAMED_2_RES_I65_N2: R42.2(N2) T4.3(PRIP)
UNNAMED_2_RES_I82_N1: R7.2(N2) R12.1(N1) R19.1(N1) R37.1(N1)
UNNAMED_2_RES_I84_N2: R41.2(N2) T3.3(PRIP)
UNNAMED_2_RES_I86_N1: R8.2(N2) R11.1(N1) R20.2(N2) R39.1(N1)
UNNAMED_2_RES_I87_N2: R19.2(N2) T3.4(SECP)
UNNAMED_2_RES_I90_N1: R20.1(N1) T3.6(SECN)
UNNAMED_2_RES_I114_N1: R45.1(N1) R47.1(N1) R55.1(N1) R57.2(N2)
UNNAMED_2_RES_I116_N2: R43.1(N1) R48.2(N2) R56.1(N1) R58.2(N2)
UNNAMED_2_RES_I120_N2: R47.2(N2) T1.6(SECN)
UNNAMED_2_RES_I123_N1: R48.1(N1) T1.4(SECP)
UNNAMED_2_RES_I125_N2: R31.2(N2) T1.1(PRIN)
UNNAMED_4_ADP3334_I83_FB: C50.2(N2) R69.1(N1) R70.2(N2) U3.3(FB)
UNNAMED_4_CAP_I156_N1: C45.1(N1) R62.2(N2) U4.44(WAKEUP)
UNNAMED_4_CAP_I159_N1: C37.1(N1) R64.2(N2) U4.42(RESET_N)
UNNAMED_4_CAP_I168_N1: C54.1(N1) U4.4(XTALOUT) Y1.3(N2)
UNNAMED_4_CAP_I172_N1: C51.1(N1) U4.5(XTALIN) Y1.1(N1)
UNNAMED_4_CN5P4GND_I166_N2: P5.2(N2) U4.9(DMINUS)
UNNAMED_4_CN5P4GND_I166_N3: P5.3(N3) U4.8(DPLUS)
UNNAMED_4_DIOLED_I67_P: CR1.A(P) R65.2(N2)
UNNAMED_4_DIOLED_I145_P: CR2.A(P) R61.2(N2)
UNNAMED_4_ICCY7C6801XA_I125_PA7: R61.1(N1) U4.40(PA7_FLAGD_SLCS_N)
UNNAMED_4_ICCY7C6801XA_I125_SCL: R60.2(N2) U2.6(SCL) U4.15(SCL)
UNNAMED_4_ICCY7C6801XA_I125_SDA: R59.2(N2) U2.5(SDA) U4.16(SDA)
VGAIN: R5.2(N2) VGAIN.1(N1)
VOCM: R6.2(N2) VOCM.1(N1)
VPS: C2.P(N1) C5.1(N1) C11.1(N1) C12.1(N1) C15.1(N1) C16.1(N1) L2.2(N2) P2.1(N1) P3.1(N1) P4.1(N1) R3.2(N2) U1.8(VPS) U1.12(VPS1) U1.16(VPS2) U1.25(VPS3) U1.29(VPS4) VPS.1(N1)
VPSD: C1.P(N1) C4.1(N1) L2.1(N1) U1.1(VPSD) VPSD.1(N1)

Pads without a net: T1 2; T2 2; T3 2; T4 2; U3 4; U4 13 18 19 20 21 22 23 24 25 29 30 31 37 38 39 45 46 47 48 49 50 51 52 54

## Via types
v1: diameter 0.508, hole 0.254, TOP to BOTTOM, 15 vias
v2: diameter 0.635, hole 0.305, TOP to BOTTOM, 165 vias
v3: diameter 0.406, hole 0.203, TOP to BOTTOM, 13 vias
v4: diameter 1.016, hole 0.508, TOP to BOTTOM, 213 vias

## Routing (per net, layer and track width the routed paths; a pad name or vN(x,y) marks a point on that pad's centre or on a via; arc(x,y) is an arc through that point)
3V3_USB: length 41.1
  TOP w0.203: C44.1 11.4,21.43 U4.11
  TOP w0.305: U3.1 23.1,19.5 22.73,19.5 22.6,19.37 U3.2 ; U4.17 14.73,23.73 v1(14.73,23.72) ; C35.1 v2(5.46,30.67) 5.46,29.98 5.65,29.79 U4.43 ; v2(5.72,20.13) C48.1 7.4,20.8 U4.3 ; U4.55 4.7,23.22 4.49,23.44 v2(3.81,23.44) ; v2(11.94,31.31) 11.4,30.77 U4.32 ; v2(15.49,29.4) C41.1 15.28,28.73 U4.27 ; C49.1 9.37,19.47 9.37,20.36 9.5,20.48 9.5,21.28 9.4,21.38 U4.7
  TOP w0.508: C38.1 v1(17.15,22.67) 17.15,22.13 R60.1 ; R59.1 v1(18.8,22.67) C39.1 ; v2(13.97,20.13) C44.1 ; C49.1 v2(10.16,19.24) C46.1 ; U2.8 v2(15.49,16.2) ; C40.1 15.33,23.72 v1(14.73,23.72) ; 23.1,19.5 23.1,20.67 C50.1 R70.1 v2(23.2,23.97) 23.2,24.71 C52.1 ; R62.1 v2(2.41,25.25) ; U2.1 v2(15.49,14.16) ; v2(3.81,23.44) C36.1 ; R64.1 v2(4.57,36.64) ; C42.1 v2(11.94,31.31)
5V_USB: length 27
  TOP w0.305: 22.86,15.31 22.6,15.57 U3.7 ; 22.86,15.31 23.1,15.55 U3.8 ; 22.86,15.31 22.86,14.76 C47.1
  TOP w0.508: P5.1 9.7,9.77 v2(9.7,9.77) ; C47.1 v1(23.2,13.19) ; R65.1 v2(27.01,15.56)
  BOTTOM w0.508: v2(27.01,15.56) 25.87,14.42 24.43,14.42 v1(23.2,13.19) 21.89,11.88 11.81,11.88 v2(9.7,9.77)
AGND: length 124
  TOP w0.305: 58.67,40.39 v3(58.42,40.64) ; 58.67,40.39 59.17,39.89 60.66,39.89 U1.19 ; 58.67,40.39 58.67,38.19 U1.13 ; v3(58.42,40.64) 57.79,41.27 ; v3(58.42,40.64) 57.17,39.39 55.97,39.39 U1.7 ; v3(58.42,40.64) 58.67,40.89 ; U1.28 58.67,40.89 ; 58.67,40.89 59.17,41.39 60.87,41.39 U1.22
  TOP w0.508: P3.3 86.36,39.32 ; P3.3 86.36,36.83 ; P3.3 85.09,38.1 ; P3.3 87.63,38.1 ; COM.1 74.68,40.64 ; COM.1 76.2,39.12 ; COM.1 77.72,40.64 ; COM.1 76.2,42.16 ; R11.2 v2(72.26,49.62) ; COMB.1 20.32,63.12 ; COMB.1 18.8,61.59 ; COMB.1 21.84,61.59 ; COMB.1 20.32,60.07 ; C2.N v4(25.4,65.41) 28.7,65.41 ; T3.1 80.06,57.1 v4(81.66,58.7) ; P4.3 81.92,39.32 ; P4.3 81.92,36.83 ; P4.3 83.19,38.1 ; P4.3 80.65,38.1 ; v2(68.67,53.21) R12.2 ; R52.2 v2(59.69,24.77) ; v2(54.74,56.52) R56.2 ; COMA.1 31.12,77.22 ; COMA.1 31.12,73.91 ; COMA.1 32.77,75.56 ; COMA.1 29.46,75.56 ; v4(77.98,18.8) 77.97,18.8 77.97,18.81 76.36,20.41 T4.1 ; P2.3 90.81,39.32 ; P2.3 92.08,38.1 ; P2.3 89.53,38.1 ; P2.3 90.81,36.83 ; v2(72.3,31.62) R14.2 ; v2(68.67,28.07) R13.2 ; v2(60.07,56.52) R55.2 ; R51.2 v2(55.12,24.77) ; v4(54.86,69.72) T1.3 ; C3.1 v2(57.4,24.77) ; R2.1 v2(50.8,26.67) ; C6.1 v2(57.4,56.52) ; T2.3 v4(59.94,11.81) ; v2(70.48,51.44) C23.1 ; C24.1 v2(70.48,29.84)
  TOP w1.27: SNS1.1 v4(9.52,40.64)
  BOTTOM w0.508: C5.2 v2(53.72,35.43) ; v2(64.14,48.77) C16.2 ; C18.2 64.14,35.31 v2(64.14,32.38) ; v2(61.72,49.02) C14.2 ; COM.1 76.2,39.12 ; COM.1 76.2,42.16 ; COM.1 74.68,40.64 ; COM.1 77.72,40.64 ; v2(55.88,45.97) C12.2 ; COMB.1 18.8,61.59 ; COMB.1 21.84,61.59 ; COMB.1 20.32,63.12 ; COMB.1 20.32,60.07 ; COMA.1 29.59,75.56 ; COMA.1 31.12,74.04 ; COMA.1 31.12,77.09 ; COMA.1 32.64,75.56 ; P3.3 86.36,39.32 ; P3.3 87.63,38.1 ; P3.3 86.36,36.83 ; P3.3 85.09,38.1 ; 59.31,30.35 v2(60.2,29.46) ; v2(62.74,44.83) 62.36,44.45 62.36,44.07 ; P4.3 81.92,36.83 ; P4.3 81.92,39.32 ; P4.3 83.19,38.1 ; C15.2 v2(62.74,32.38) ; P2.3 90.81,39.32 ; P2.3 89.53,38.1 ; P2.3 92.08,38.1 ; P2.3 90.81,36.86 ; v2(59.94,49.02) R4.2 ; C13.2 v2(61.09,32.38)
  vias: v2(45.21,3.81) v2(45.21,2.54) v2(45.21,1.27) v2(45.34,80.01) v2(45.34,78.74) v2(45.34,77.47) v2(54.1,3.81) v2(54.1,2.54) v2(54.1,1.27) v2(54.23,80.01) v2(54.23,78.74) v2(54.23,77.47) v2(55.12,44.2) v2(59.94,3.81) v2(59.94,2.54) v2(59.94,1.27) v2(60.58,80.01) v2(60.58,78.74) v2(60.58,77.47) v2(68.83,3.81) v2(68.83,2.54) v2(68.83,1.27) v2(69.47,80.01) v2(69.47,78.74) v2(69.47,77.47) v2(75.69,73.7) v2(75.81,7.45) v2(76.59,74.59) v2(76.71,6.56) v2(77.48,75.5) v2(77.61,5.66) v2(81.97,67.41) v2(82.1,13.74) v2(82.87,68.31) v2(83,12.84) v2(83.77,69.21) v2(83.9,11.95) v2(86.46,62.92) v2(86.59,18.23) v2(87.36,63.82) v2(87.49,17.33) v2(88.26,64.72) v2(88.38,16.43) v2(92.75,56.64) v2(92.88,24.52) v2(93.64,57.54) v2(93.77,23.62) v2(94.55,58.43) v2(94.67,22.72) v3(57.15,41.91) v3(57.15,40.64) v3(57.15,39.37) v3(58.42,41.91) v3(58.42,39.37) v3(59.69,41.91) v3(59.69,40.64) v3(59.69,39.37) v4(1.91,69.22) v4(1.91,64.14) v4(1.91,59.05) v4(1.91,53.98) v4(1.91,48.9) v4(1.91,43.81) v4(1.91,40.64) v4(6.98,74.3) v4(6.98,69.22) v4(6.98,64.14) v4(6.98,59.05) v4(6.98,53.98) v4(6.98,48.9) v4(6.98,43.81) v4(6.98,40.64) v4(12.07,74.3) v4(12.07,69.22) v4(12.07,64.14) v4(12.07,59.05) v4(12.07,53.98) v4(12.07,48.9) v4(12.07,43.81) v4(12.07,40.64) v4(17.15,74.3) v4(17.15,69.22) v4(17.15,64.14) v4(17.15,59.05) v4(17.15,53.98) v4(17.15,48.9) v4(17.15,43.81) v4(17.15,40.64) v4(22.23,79.38) v4(22.23,74.3) v4(22.23,59.05) v4(22.23,53.98) v4(22.23,48.9) v4(22.23,43.81) v4(22.23,40.64) v4(27.31,79.38) v4(27.31,62.87) v4(27.31,59.05) v4(27.31,53.98) v4(27.31,48.9) v4(27.31,43.81) v4(32.39,79.38) v4(32.39,62.87) v4(32.39,48.9) v4(32.39,35.56) v4(32.39,30.48) v4(32.39,20.32) v4(32.39,15.24) v4(32.39,5.08) v4(32.39,1.91) v4(37.47,79.38) v4(37.47,62.87) v4(37.47,48.9) v4(37.47,30.48) v4(37.47,20.32) v4(37.47,15.24) v4(37.47,5.08) v4(37.47,1.91) v4(41.91,30.48) v4(42.55,79.38) v4(42.55,74.3) v4(42.55,71.75) v4(42.55,59.05) v4(42.55,53.98) v4(42.55,48.9) v4(42.55,43.81) v4(42.55,20.32) v4(42.55,15.24) v4(42.55,8.89) v4(42.55,5.08) v4(42.55,1.91) v4(43.81,62.87) v4(46.36,48.9) v4(46.36,43.81) v4(46.36,30.48) v4(46.36,25.4) v4(46.36,20.32) v4(46.36,15.24) v4(47.62,62.87) v4(47.62,59.05) v4(48.26,74.3) v4(48.26,71.75) v4(48.26,3.17) v4(48.9,30.48) v4(48.9,25.4) v4(48.9,20.32) v4(48.9,15.24) v4(49.53,66.67) v4(49.53,64.14) v4(50.16,59.05) v4(50.16,43.81) v4(51.44,74.3) v4(51.44,71.75) v4(51.44,8.89) v4(51.44,6.35) v4(51.44,3.17) v4(52.32,66.67) v4(52.32,64.14) v4(52.7,53.34) v4(55.25,74.3) v4(55.25,71.75) v4(55.25,8.89) v4(55.25,6.35) v4(57.15,3.17) v4(59.05,8.89) v4(59.05,6.35) v4(59.69,74.3) v4(59.69,71.75) v4(60.96,27.94) v4(62.23,53.34) v4(62.48,66.67) v4(62.48,64.14) v4(62.87,8.89) v4(62.87,6.35) v4(62.87,3.17) v4(63.5,74.3) v4(63.5,71.75) v4(64.14,59.05) v4(64.14,27.94) v4(65.41,66.67) v4(65.41,64.14) v4(65.41,53.98) v4(66.04,24.13) v4(66.04,20.32) v4(66.04,17.14) v4(66.04,12.7) v4(66.04,8.89) v4(66.04,6.35) v4(66.04,3.17) v4(66.67,74.3) v4(66.67,71.75) v4(67.31,59.05) v4(71.12,17.14) v4(71.12,12.7) v4(71.12,8.89) v4(71.12,6.35) v4(71.75,74.3) v4(71.75,71.75) v4(71.75,66.67) v4(71.75,64.14) v4(72.39,20.96) v4(74.93,12.7) v4(74.93,3.17) v4(75.56,22.86) v4(76.84,14.61) v4(77.47,24.77) v4(77.47,10.16) v4(78.11,65.41) v4(78.74,67.94) v4(78.74,12.7) v4(78.74,8.26) v4(79.38,27.94) v4(81.28,20.32) v4(81.28,16.51) v4(81.28,10.8) v4(82.55,34.92) v4(82.55,29.84) v4(83.19,65.41) v4(83.19,60.33) v4(85.72,53.98) v4(85.72,50.16) v4(85.72,22.86) v4(85.85,58.42) v4(87.63,34.92) v4(88.27,25.4) v4(88.9,19.05) v4(92.08,21.59) v4(92.71,53.98) v4(92.71,50.16) v4(92.71,45.09) v4(92.71,34.92) v4(92.71,29.97) v4(97.79,53.98) v4(97.79,50.16) v4(97.79,45.09) v4(97.79,40.01) v4(97.79,34.92) v4(97.79,29.84) v4(97.79,26.04)
DGND: length 74.7
  TOP w0.203: v1(13.46,21.15) 12.9,21.71 U4.14 ; v1(12.7,21.02) 12.32,21.02 11.9,21.44 U4.12
  TOP w0.305: U4.2 6.9,21.32 6.6,21.02 v1(6.22,21.02) ; C27.2 v2(45.34,52.58) ; U1.2 55.97,41.89 54.76,41.89 v2(54.1,42.55) ; v1(10.9,21.02) U4.10 ; C4.2 v2(51.69,47.12) ; U4.41 6.9,31.73 v2(7.37,32.2) ; U4.56 5.65,21.98 v2(5.64,21.98) U4.1 ; v1(14.6,28.13) 14.51,28.22 U4.26 ; R1.2 v2(51.44,34.8) ; v1(8.9,20.96) 8.9,20.96 U4.6 ; v1(4.73,24.22) U4.53
  TOP w0.508: C52.2 v2(24.77,26.7) ; DGND.1 16.89,30.48 ; DGND.1 19.94,30.48 ; DGND.1 18.41,28.96 ; DGND.1 18.41,32 ; Y1.4 10.88,12.22 v2(11.43,12.77) ; v2(5.72,17.21) 5.72,16.28 C54.2 ; R69.2 v2(20.19,26.44) ; v2(28.83,9.21) 27.46,9.21 CR2.C ; C40.2 v2(15.49,25.85) C41.2 ; C51.2 v2(10.76,14.99) ; C35.2 v2(3.18,31.69) ; C37.2 v2(6.48,35.88) ; C39.2 v2(18.8,25.85) ; C46.2 v1(10.16,17.97) C49.2 ; C28.2 v4(43.81,32.26) ; C48.2 v2(6.73,17.85) ; P5.4 12.1,9.71 v2(12.5,10.1) 12.9,9.69 P5.5 ; v2(16.76,10.86) U2.2 ; C45.2 v2(2.92,30.04) ; C38.2 v2(17.15,25.85) ; U2.7 v2(16.76,16.2) ; C47.2 v2(21.5,13.28) ; v2(19.3,10.86) U2.4 ; U2.3 v2(18.03,10.86) ; C36.2 v2(3.81,20.01) ; Y1.2 v1(7.79,14.88) ; C44.2 v2(13.97,18.86) ; C42.2 v2(11.94,35.37) ; C1.N v4(36.83,65.41) L1.1 ; CR1.C v2(28.96,14.42)
  TOP w1.27: 9.52,37.85 v4(9.52,37.47)
  BOTTOM w0.508: DGND.1 19.94,30.48 ; DGND.1 18.41,31.88 ; DGND.1 18.41,28.96 ; DGND.1 16.89,30.48
  vias: v2(6.35,8.45) v2(6.35,7.05) v2(6.35,2.99) v2(6.35,1.59) v2(7.37,8.45) v2(7.37,7.05) v2(7.37,2.99) v2(7.37,1.59) v2(8.13,27.5) v2(8.13,25.98) v2(8.13,24.45) v2(9.65,27.5) v2(9.65,25.98) v2(9.65,24.45) v2(11.18,27.5) v2(11.18,25.98) v2(11.18,24.45) v2(11.43,6.04) v2(11.43,4.51) v2(15.24,8.45) v2(15.24,7.05) v2(15.24,2.99) v2(15.24,1.59) v2(16.26,8.45) v2(16.26,7.05) v2(16.26,2.99) v2(16.26,1.59) v2(21.84,17.34) v2(22.86,17.85) v4(1.91,37.47) v4(1.91,32.38) v4(1.91,19.69) v4(1.91,13.97) v4(1.91,8.26) v4(1.91,1.91) v4(6.98,37.47) v4(11.43,1.91) v4(12.07,37.47) v4(17.15,37.47) v4(17.15,27.3) v4(17.78,9.53) v4(18.41,1.91) v4(23.5,9.53) v4(23.5,5.08) v4(23.5,1.91) v4(28.58,37.47) v4(28.58,34.92) v4(28.58,31.75) v4(28.58,20.32) v4(28.58,5.08) v4(28.58,1.91)
CLK: length 41.1
  TOP w0.203: U4.35 9.9,30.93 v3(9.52,31.31)
  TOP w0.305: R30.1 38.1,34.92 36.2,36.83 v2(36.2,40.64)
  BOTTOM w0.203: v2(36.2,40.64) 26.42,40.64 20.32,34.54 12.76,34.54 v3(9.52,31.31)
DATA: length 37.5
  TOP w0.203: U4.34 10.4,31.19 v3(10.29,31.31)
  TOP w0.305: R33.1 v2(36.2,25.4)
  BOTTOM w0.203: v3(10.29,31.31) 12.76,33.78 24.64,33.78 33.02,25.4 v2(36.2,25.4)
LE: length 52
  TOP w0.203: U4.36 9.4,30.67 v3(8.76,31.31)
  TOP w0.305: v2(36.2,55.88) R29.1
  BOTTOM w0.203: v2(36.2,55.88) 36.2,51.44 20.07,35.31 12.76,35.31 v3(8.76,31.31)
SDO: length 55.2
  TOP w0.203: U4.33 10.9,31.16 v3(11.05,31.31)
  TOP w0.305: v2(36.2,10.16) R34.1
  BOTTOM w0.203: v3(11.05,31.31) 12.76,33.02 24.38,33.02 29.85,27.56 29.85,13.34 33.02,10.16 v2(36.2,10.16)
TRIM: length 12.9
  TOP w0.305: U1.9 56.35,38.19 56.01,37.85 v2(56.01,37.34) 56.01,35.31 55.18,34.48 52.9,34.48 TRIM.1 R2.2
UNNAMED_2_ADRF6510_I1_CLK: length 16.5
  TOP w0.305: U1.4 55.97,40.89 54.35,40.89 51.94,38.48 51.05,38.48 47.5,34.92 C28.1 R30.2
UNNAMED_2_ADRF6510_I1_DATA: length 21.4
  TOP w0.305: U1.5 55.97,40.39 54.99,40.39 52.45,37.85 51.56,37.85 45.09,31.37 45.09,27.3 R33.2
UNNAMED_2_ADRF6510_I1_ENBL: length 54.4
  TOP w0.305: U1.32 56.67,43.91 52.32,48.26 v2(52.32,51.18)
  BOTTOM w0.305: v2(52.32,51.18) 60.71,51.18 61.85,52.32 80.39,52.32 88.27,44.45 88.27,43.18 P2.2
UNNAMED_2_ADRF6510_I1_GAIN: length 3
  TOP w0.305: U1.21 60.87,40.89 61.72,40.89 v2(62.36,41.53)
  BOTTOM w0.305: C17.2 v2(62.36,41.53)
UNNAMED_2_ADRF6510_I1_GNSW: length 38.1
  TOP w0.305: U1.27 59.17,43.09 59.17,44.31 59.56,44.7 v2(59.56,45.47) 59.56,45.59 v2(64.14,50.16)
  BOTTOM w0.254: R4.1 59.56,46.36 v2(59.56,45.47)
  BOTTOM w0.305: P3.2 83.82,43.18 83.82,44.45 77.72,50.55 68.83,50.55 68.45,50.93 64.9,50.93 v2(64.14,50.16)
UNNAMED_2_ADRF6510_I1_INM1: length 4.9
  TOP w0.152: U1.30 57.67,43.09 57.67,46.91 C9.2
UNNAMED_2_ADRF6510_I1_INM2: length 4.9
  TOP w0.152: C8.1 57.67,34.37 57.67,38.19 U1.11
UNNAMED_2_ADRF6510_I1_INP1: length 4.9
  TOP w0.152: C10.2 57.17,46.88 57.17,43.09 U1.31
UNNAMED_2_ADRF6510_I1_INP2: length 4.9
  TOP w0.152: U1.10 57.17,38.19 57.17,34.4 C7.1
UNNAMED_2_ADRF6510_I1_LE: length 19
  TOP w0.305: R29.2 C27.1 47.62,47.88 54.11,41.39 55.97,41.39 U1.3
UNNAMED_2_ADRF6510_I1_OFDS: length 36.8
  TOP w0.305: U1.14 59.17,37.95 59.17,36.33 59.31,36.2 v2(59.31,35.81) 59.94,35.18 59.94,31.5 v2(61.02,30.42)
  BOTTOM w0.305: v2(61.02,30.42) 63.56,30.42 64.14,29.84 67.95,29.84 71.12,33.02 76.84,33.02 79.38,35.56 79.38,38.1 P4.2 ; R3.1 v2(59.31,35.81)
UNNAMED_2_ADRF6510_I1_OFS1: length 4.5
  TOP w0.305: U1.26 59.67,43.09 59.67,43.92 v2(61.21,45.47)
  BOTTOM w0.254: C14.1 61.21,46.23 v2(61.21,45.47)
UNNAMED_2_ADRF6510_I1_OFS2: length 4.1
  TOP w0.305: v2(61.09,35.81) 59.67,37.23 59.67,37.97 59.67,37.97 U1.15
  BOTTOM w0.254: v2(61.09,35.81) C13.1
UNNAMED_2_ADRF6510_I1_OPM1: length 5.3
  TOP w0.152: C20.1 63.67,44.24 61.32,41.89 61.11,41.89 U1.23 ; U1.23 60.86,41.88 60.73,41.88 60.74,41.89 U1.23
UNNAMED_2_ADRF6510_I1_OPM2: length 4.8
  TOP w0.152: C21.1 63.67,37.17 61.45,39.39 60.87,39.39 U1.18
UNNAMED_2_ADRF6510_I1_OPP1: length 4.6
  TOP w0.152: U1.24 61.19,42.39 63.41,44.62 C19.1
UNNAMED_2_ADRF6510_I1_OPP2: length 4.4
  TOP w0.152: C22.1 63.29,36.79 61.19,38.89 U1.17
UNNAMED_2_ADRF6510_I1_SDO: length 33.9
  TOP w0.305: R34.2 47.62,32.77 51.69,36.83 R1.1 52.45,36.83 55.19,39.57 55.19,39.59 55.48,39.87 55.49,39.87 55.51,39.89 55.97,39.89 U1.6
UNNAMED_2_ADRF6510_I1_VOCM: length 3.1
  TOP w0.305: v2(62.36,39.75) 61.72,40.39 60.87,40.39 U1.20
  BOTTOM w0.305: C18.1 v2(62.36,39.75)
UNNAMED_2_CAP_I21_N2: length 9.8
  TOP w0.152: C8.2 58.42,28.19 P1.2 61.98,24.64 R54.1
UNNAMED_2_CAP_I22_N2: length 9.8
  TOP w0.152: R53.1 52.83,24.64 P1.1 56.39,28.19 C7.2
UNNAMED_2_CAP_I31_N2: length 3.2
  TOP w0.305: T2.5 C3.2
UNNAMED_2_CAP_I52_N2: length 3.5
  TOP w0.305: T4.5 74.53,25.8 C24.2
UNNAMED_2_CAP_I59_N2: length 10
  TOP w0.152: R9.1 73.47,33.15 P8.1 68.56,33.15 66,35.71 C21.2
UNNAMED_2_CAP_I60_N2: length 10.1
  TOP w0.152: C22.2 64.74,34.46 67.29,31.91 P8.2 67.29,26.75 R10.1
UNNAMED_2_CAP_I89_N2: length 3.5
  TOP w0.305: C23.2 74.4,55.35 74.45,55.3 T3.5
UNNAMED_2_CAP_I96_N2: length 9.9
  TOP w0.152: R7.1 66.67,53.91 P7.1 66.67,48.75 64.87,46.95 C19.2
UNNAMED_2_CAP_I97_N2: length 9.8
  TOP w0.152: C20.2 66.13,45.69 67.91,47.48 P7.2 72.82,47.48 R8.1
UNNAMED_2_CAP_I111_N1: length 9.7
  TOP w0.152: R57.1 61.85,56.52 P6.1 58.42,53.09 C9.1
UNNAMED_2_CAP_I112_N1: length 9.7
  TOP w0.152: C10.1 56.39,53.09 P6.2 52.96,56.52 R58.1
UNNAMED_2_CAP_I121_N2: length 3.4
  TOP w0.305: 57.4,62.36 C6.2
UNNAMED_2_CNBNC5P_I37_CNTR: length 11.6
  TOP w0.305: R32.1 R46.2 49.78,9.91 INP2.1
UNNAMED_2_CNBNC5P_I39_CNTR: length 8.8
  TOP w0.305: R44.2 64.52,10.41 INM2_SE_P.1
UNNAMED_2_CNBNC5P_I62_CNTR: length 10.2
  TOP w0.305: R42.1 84.72,24.82 R38.2 86.28,24.82 90.51,20.6 OPM2_SE_P.1
UNNAMED_2_CNBNC5P_I63_CNTR: length 7.7
  TOP w0.305: R40.2 75.38,14.2 79.73,9.85 OPP2.1
UNNAMED_2_CNBNC5P_I80_CNTR: length 10.5
  TOP w0.305: R41.1 77.45,63.5 R37.2 75.51,67.23 OPP1.1
UNNAMED_2_CNBNC5P_I81_CNTR: length 7.9
  TOP w0.305: OPM1_SE_P.1 85.78,55.95 R39.2
UNNAMED_2_CNBNC5P_I127_CNTR: length 11.8
  TOP w0.305: INM1_SE_P.1 65.02,71.25 R45.2 R31.1
UNNAMED_2_CNBNC5P_I129_CNTR: length 9.2
  TOP w0.305: 50.93,69.98 49.78,71.12 INP1.1
UNNAMED_2_RES_I24_N2: length 13.1
  TOP w0.152: R51.1 R53.2 50.93,20.45 R49.1 R46.1
UNNAMED_2_RES_I26_N2: length 13.1
  TOP w0.152: R44.1 R50.2 63.88,20.45 R54.2 R52.1
UNNAMED_2_RES_I29_N2: length 2.7
  TOP w0.152: T2.6 R49.2
UNNAMED_2_RES_I32_N1: length 2.7
  TOP w0.152: R50.1 T2.4
UNNAMED_2_RES_I34_N2: length 2.9
  TOP w0.305: T2.1 R32.2
UNNAMED_2_RES_I50_N1: length 12.9
  TOP w0.152: R38.1 83.88,25.73 R35.1 79.18,30.42 78.22,31.38 R9.2 73.89,30.03 R14.1
UNNAMED_2_RES_I50_N2: length 2.7
  TOP w0.152: T4.4 76.36,27.6 R35.2
UNNAMED_2_RES_I51_N1: length 2.8
  TOP w0.152: T4.6 70.81,22.05 R36.1
UNNAMED_2_RES_I51_N2: length 12.7
  TOP w0.152: R13.1 70.3,26.44 R10.2 68.95,22.1 R36.2 69.92,21.14 R40.1
UNNAMED_2_RES_I65_N2: length 2.8
  TOP w0.305: R42.2 80,24 T4.3
UNNAMED_2_RES_I82_N1: length 12.6
  TOP w0.152: R37.1 69.96,59.9 R19.1 68.95,58.83 R7.2 R12.1
UNNAMED_2_RES_I84_N2: length 2.7
  TOP w0.305: R41.2 76.45,60.7 T3.3
UNNAMED_2_RES_I86_N1: length 12.4
  TOP w0.152: R39.1 79.32,50.74 R20.2 78.49,49.9 R8.2 73.89,51.25 R11.1
UNNAMED_2_RES_I87_N2: length 2.8
  TOP w0.152: R19.2 70.85,58.92 72.67,57.1 T3.4
UNNAMED_2_RES_I90_N1: length 2.7
  TOP w0.152: R20.1 76.54,53.51 T3.6
UNNAMED_2_RES_I114_N1: length 12.5
  TOP w0.152: R55.1 R57.2 63.88,60.96 R47.1 R45.1
UNNAMED_2_RES_I116_N2: length 12.4
  TOP w0.152: R43.1 R48.2 50.93,60.96 R58.2 R56.1
UNNAMED_2_RES_I120_N2: length 2.7
  TOP w0.152: R47.2 59.94,62.36
UNNAMED_2_RES_I123_N1: length 2.7
  TOP w0.152: 54.86,62.36 R48.1
UNNAMED_2_RES_I125_N2: length 2.7
  TOP w0.305: R31.2 T1.1
UNNAMED_4_ADP3334_I83_FB: length 6.1
  TOP w0.203: U3.3 22.1,20.17 C50.2
  TOP w0.508: R69.1 21.46,22.84 R70.2 C50.2
UNNAMED_4_CAP_I156_N1: length 3.7
  TOP w0.203: U4.44 3.98,28.73 C45.1 3.94,27.21 R62.2
UNNAMED_4_CAP_I159_N1: length 5.6
  TOP w0.203: R64.2 4.74,33.6 C37.1 6.4,33.52 U4.42
UNNAMED_4_CAP_I168_N1: length 11.4
  TOP w0.203: U4.4 7.9,16.77 C54.1 6.52,15.39 6.52,12.59 6.9,12.22 Y1.3
UNNAMED_4_CAP_I172_N1: length 8.8
  TOP w0.203: U4.5 8.4,21.97 8.4,16.72 C51.1 9.52,15.6 9.52,14.29 Y1.1
UNNAMED_4_CN5P4GND_I166_N2: length 28.4
  TOP w0.203: P5.2 10.54,7.81 10.54,4.26 11.05,3.75 14.1,3.75 14.86,4.51 14.86,5.91 13.84,6.93 13.84,15.82 12.07,17.59 12.07,20.13 11.68,20.51 10.67,20.51 10.4,20.78 U4.9
UNNAMED_4_CN5P4GND_I166_N3: length 16.9
  TOP w0.203: P5.3 11.3,10.61 13.08,12.39 13.08,15.94 11.68,17.34 11.68,19.88 11.56,20.01 10.41,20.01 10.03,20.39 10.03,21.35 9.9,21.48 U4.8
UNNAMED_4_DIOLED_I67_P: length 2.2
  TOP w0.203: R65.2 25.24,16.51 CR1.A
UNNAMED_4_DIOLED_I145_P: length 2.2
  TOP w0.203: R61.2 25.12,11.31 CR2.A
UNNAMED_4_ICCY7C6801XA_I125_PA7: length 33.7
  TOP w0.203: R61.1 v2(27.81,11.37) ; U4.40 7.4,30.84 v2(7.62,31.06)
  BOTTOM w0.203: v2(27.81,11.37) 27.81,16.64 19.69,24.77 15.24,24.77 10.98,29.02 9.65,29.02 v2(7.62,31.06)
UNNAMED_4_ICCY7C6801XA_I125_SCL: length 7.6
  TOP w0.203: U4.15 13.65,21.85 15.37,20.13 16.68,20.13 R60.2 18.03,18.77 U2.6
UNNAMED_4_ICCY7C6801XA_I125_SDA: length 9.7
  TOP w0.203: v1(17.78,20.9) 17.95,20.9 R59.2 19.3,19.54 U2.5 ; v1(15.49,20.9) 14.48,21.91 14.48,23.05 14.31,23.22 U4.16
  BOTTOM w0.203: v1(15.49,20.9) v1(17.78,20.9)
VGAIN: length 14.6
  BOTTOM w0.305: VGAIN.1 74.3,45.72 73.03,44.45 66.04,44.45 63.88,42.29 63.88,41.78 R5.2
VOCM: length 15
  BOTTOM w0.305: R6.2 63.63,38.61 66.8,35.43 VOCM.1
VPS: length 126.9
  TOP w0.305: U1.16 60.17,37.87 v2(60.83,37.21) ; L2.2 25.4,70.48 VPS.1 ; U1.12 58.17,38 58.17,38 58.17,36.83 v2(58.42,36.58) ; U1.25 60.17,43.28 v2(60.83,43.94) ; U1.8 55.5,38.89 54.86,38.25 v2(54.86,37.85) ; v2(58.42,44.83) 58.17,44.58 58.17,43.09 U1.29 ; P2.1 P3.1 P4.1
  BOTTOM w0.254: v2(60.83,43.94) 60.83,44.07 63.37,46.61 C16.1
  BOTTOM w0.305: v2(58.42,44.83) 59.95,44.83 v2(60.83,43.94) v2(60.83,37.21) ; v2(58.42,44.83) 58.42,45.72 C12.1 ; v2(58.42,44.83) 55.5,44.83 50.16,50.16 50.16,54.61 37.47,67.31 33.66,67.31 VPS.1 ; C11.1 R3.2 58.67,33.4 58.42,33.66 v2(58.42,36.58) ; v2(58.42,36.58) 58.35,36.51 55.05,36.51 54.86,36.7 v2(54.86,37.85) ; v2(58.42,36.58) 60.2,36.58 v2(60.83,37.21) ; P4.1 76.84,48.26 74.3,48.26 71.75,45.72 65.91,45.72 64.9,46.74 C16.1 ; v2(60.83,37.21) 62.74,35.31 C15.1
VPSD: length 48.8
  TOP w0.305: L2.1 36.83,70.48 ; 36.83,70.48 41.91,70.48 48.77,63.63 48.77,48.13 52.2,44.7 C4.1 53.59,44.7 54.48,43.81 54.48,43.43 55.53,42.39 U1.1 ; 36.83,70.48 VPSD.1

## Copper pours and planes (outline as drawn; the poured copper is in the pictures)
3V3_USB on L3_GND: 0.64,0.64 0.64,38.73 29.85,38.73 29.85,0.64
AGND on TOP: 17.78,80.65 73.66,80.65 99.06,55.25 99.06,26.04 73.66,0.63 30.48,0.63 30.48,39.37 0.64,39.37 0.64,75.56 17.78,75.56 ; 16 cut-outs
AGND on BOTTOM: 30.48,39.37 0.64,39.37 0.64,80.65 73.66,80.65 99.06,55.25 99.06,26.04 73.66,0.63 30.48,0.63 ; 6 cut-outs
AGND on L2_GND: 0.64,0.63 0.64,80.65 73.66,80.65 99.06,55.25 99.06,26.04 73.66,0.63 ; 5 cut-outs
AGND on L3_GND: 0.64,39.37 0.64,80.65 73.66,80.65 99.06,55.25 99.06,26.04 73.66,0.63 30.48,0.63 30.48,39.37
DGND on TOP: 0.64,0.64 0.64,38.73 29.85,38.73 29.85,0.64 ; 2 cut-outs
DGND on BOTTOM: 0.64,0.64 0.64,38.73 29.85,38.73 29.85,0.64 ; 1 cut-out
DGND on L2_GND: 53.34,41.27 55.25,41.27 55.25,46.36 48.9,52.7 48.9,63.5 43.18,69.22 34.92,69.22 32.39,66.67 32.39,63.5 29.85,60.96 29.85,38.73 0.64,38.73 0.64,0.63 35.56,0.63 35.56,5.72 45.09,5.72 45.09,34.29 53.34,34.29

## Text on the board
Ref Des/Silkscreen Bottom: SECONDARY SIDE | 08-A02101 REV.G Z
TOP: ADRF6510 Z | 08-A02101 REV.G
PAGE_OUTLINE: B | C | D | E | F | G | REVISED CIRCUIT | REVISED PER ALP2101H | REVISED PER ALP2101G | 10/08 | 06/09 | 04/10 | 07/10 | 16JUN11 | 17AUG11 | L. SMALL | R.SONI | JOEL DOBLER
DIMENSION: SEE NOTE 15 | MAX DIAMETER
User.9: 15.    VIAS IN THIS AREA TO BE NON-CONDUCTIVE FILLED AND GROUND | FLUSH PRIOR TO OVER PLATING
User.10: MATERIALS;     IS410/370HR IN ACCORDANCE WITH IPC-L-130 (LATEST REV.) GLASS FABRIC | BASE, EPOXY RESIN, FIRE RESISTANT. | 14.    IPC NETLIST TESTING TO BE DONE WITH NETLIST PROVIDED PRIOR TO FABRICATION. | ANY INTENTIONAL SHORTS WILL BE DEFINED IN READ_ME.2 FILE.
User.11: LAYER 2 GROUND | 08-      -07
User.12: LAYER 3 GROUND | 08-      -08
User.13: BUMPLET PRIMARY | 08-      -12
User.16: 1:1
User.17: 2:1 | 1 | ASSEMBLY | 01 | G
User.19: CIRCUIT SIDE
User.20: 1. ADD JUMPERS (A011-0002-038) PER JUMPER CONFIGURATION TABLE. | POSITION | P2 | P3 | P4 | PIN 1 | JUMPER CONFIGURATION | PIN 2 | PIN 3 | NOTES | COMPONENT SIDE
User.25: FIGURE | SIZE | 8.0 | 10.0 | 12.0 | 20.0 | 40.0 | 45.0 | 63.0 | 35.0 | 120.0 | PLATED | NON-PLATED | FINISHED HOLES IN MILS | ALL UNITS ARE IN MILS | QTY | 13 | 15 | 165 | 213 | 8 | 9 | 11 | 2 | 4 | TOLERANCE/NOTES
